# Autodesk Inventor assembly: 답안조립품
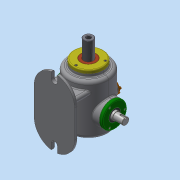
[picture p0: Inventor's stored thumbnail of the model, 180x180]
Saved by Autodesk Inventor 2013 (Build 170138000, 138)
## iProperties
Created: 2018-02
Part Number: 답안조립품
Document SubType Name: Assembly
Designer: dgall
Mass: 5400.15 g
Surface Area: 3901.66 cm^2
Volume: 1791.93 cm^3
Density: 3.01359 g/cm^3
Author: dgall
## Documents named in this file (16)
- C:\Users\dgall\Desktop\380207V1009\답안조립품.iam
- C:\Users\dgall\Desktop\380207V1009\본체.ipt
- C:\Users\dgall\Desktop\380207V1009\가변스프링.ipt
- C:\Users\dgall\Desktop\380207V1009\본체커버.ipt
- C:\Users\dgall\Desktop\380207V1009\부시.ipt
- C:\Users\dgall\Desktop\380207V1009\상부 캡.ipt
- C:\Users\dgall\Desktop\380207V1009\슬라이드 커버.ipt
- C:\Users\dgall\Desktop\380207V1009\슬라이드.ipt
- C:\Users\dgall\Desktop\380207V1009\오일실.ipt
- 오일실.ipt
- C:\Users\dgall\Desktop\380207V1009\축 커버-1.ipt
- C:\Users\dgall\Desktop\380207V1009\축 커버-2.ipt
- C:\Users\dgall\Desktop\380207V1009\편심축.ipt
- C:\Users\dgall\Desktop\380207V1009\베어링 6205.ipt
- 베어링 6205.ipt
- C:\Users\dgall\Desktop\380207V1009\볼트 M4.ipt
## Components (1 placed, 1 different names)
1. 가변스프링:1
